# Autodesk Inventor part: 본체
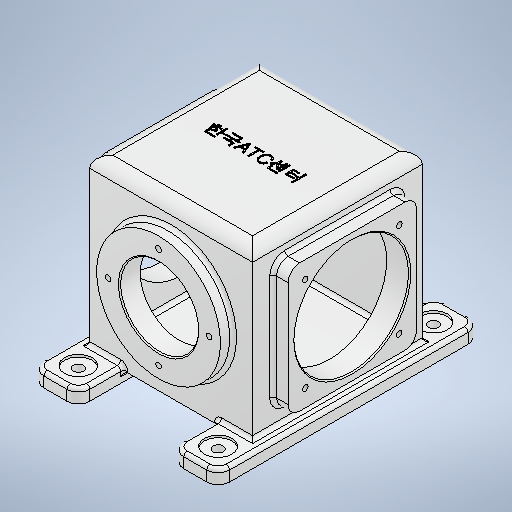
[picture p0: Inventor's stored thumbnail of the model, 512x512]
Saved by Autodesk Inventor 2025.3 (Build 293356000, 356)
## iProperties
Created: 2026-01
Part Number: 본체
Material: 알루미늄 6061
Document SubType Name: Modeling
Designer: PC01-12
Density: 2.7 g/cm^3
Appearance: 알루미늄 - 평지
Mass: 2756.19 g
Surface Area: 2492.21 cm^2
Volume: 1020.81 cm^3
Author: PC01-12
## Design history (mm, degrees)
sketch "스케치1"
  geometry: L1 (-71, -74)-(71, -74); L2 (71, -74)-(71, 74); L3 (71, 74)-(-71, 74); L4 (-71, 74)-(-71, -74); L5 (-71, -74)-(71, 74); L6 (71, -74)-(-71, 74); 1 further point
  constraints: 12 end point, 2 midpoint, 2 parallel, 1 horizontal, 1 perpendicular
  dimensions: "d0" = 142 distance of L3.end L2.end; "d1" = 148 distance of L2.end L1.end
extrude "돌출1" new body sketch "스케치1" stored distance "d2" = 148; taper "d3" = 0 deg
sketch "스케치2"
  geometry: C1 r 54 at (0, 0); 1 further point
  constraints: 1 centre point, 1 coincident
  dimensions: "d4" = 108 diameter of C1
extrude "돌출2" join sketch "스케치2" distance "d5" = 11; taper "d6" = 0 deg
sketch "스케치3"
  geometry: C1 r 34 at (0, 0); 1 further point
  constraints: 1 centre point, 1 coincident
  dimensions: "d7" = 68 diameter of C1
extrude "돌출3" cut sketch "스케치3" distance "d8" = 50; taper "d9" = 0 deg
sketch "스케치4" dims "d10" = 88
  geometry: 3 further points
  constraints: 2 vertical alignment, 1 coincident, 2 other
hole "구멍1" sketch "스케치4" at (0, 44) diameter "d11" = 4.917; stored, may be unused: countersink angle "d15" = 90 deg, drill point angle "d17" = 118 deg; dims "d12" = 12, "d13" = 4, "d14" = 2, "d16" = 14
sketch "스케치5"
  geometry: L1 (148, 148)-(0, 148) reference; L2 (0, 0)-(0, 148) reference; L3 (0, 0)-(148, 0) reference; L4 (148, 148)-(148, 0) reference; L5 (18, 130)-(130, 130); L6 (130, 130)-(130, 18); L7 (130, 18)-(18, 18); L8 (18, 18)-(18, 130); 1 further point
  constraints: 8 end point, 3 other
  dimensions: "d43" = 112 distance of L5.start L5.end
extrude "돌출4" join sketch "스케치5" distance "d22" = 13; taper "d23" = 0 deg
sketch "스케치6"
  geometry: C1 r 50 at (74, 74); 1 further point
  constraints: 1 centre point, 1 coincident
  dimensions: "d24" = 100 diameter of C1
extrude "돌출5" cut sketch "스케치6" stored distance "d25" = 148; taper "d26" = 0 deg
sketch "스케치7"
  geometry: L1 (18, 18)-(130, 18) reference; L2 (130, 18)-(130, 130) reference; L3 (130, 130)-(18, 130) reference; L4 (18, 130)-(18, 18) reference; L5 (33, 115)-(115, 115); L6 (115, 115)-(115, 33); L7 (115, 33)-(33, 33); L8 (33, 33)-(33, 115); C1 r 50 at (74, 74) reference; 5 further points
  constraints: 8 end point, 4 coincident, 3 other
  dimensions: "d44" = 82 distance of L5.start L5.end
hole "구멍2" sketch "스케치7" at (33, 115), (115, 115), (115, 33), (33, 33) diameter "d28" = 4.917; stored, may be unused: countersink angle "d32" = 90 deg, drill point angle "d34" = 118 deg; dims "d29" = 12, "d30" = 4, "d31" = 2, "d33" = 14
node "작업 평면1"
sketch "스케치8"
  geometry: L1 (-41, 114)-(-81, 114); L2 (-81, 114)-(-81, -114); L3 (-81, -114)-(-41, -114); L4 (-41, -114)-(-41, 114); L5 (81, 114)-(41, 114); L6 (41, 114)-(41, -114); L7 (41, -114)-(81, -114); L8 (81, -114)-(81, 114); L9 (0, -105.8)-(0, 116.8) reference; L10 (117.6, 0)-(-117.6, 0) reference; 1 further point
  constraints: 16 end point, 4 parallel, 2 horizontal, 2 perpendicular, 3 other
  dimensions: "d36" = 162 distance between parallel lines of L2 L8; "d37" = 40 distance between parallel lines of L6 L8; "d38" = 40 distance between parallel lines of L2 L4; "d39" = 228 distance between parallel lines of L1 L3; "d40" = 228 distance between parallel lines of L7 L5
extrude "돌출6" join sketch "스케치8" distance "d41" = 12; taper "d42" = 0 deg
sketch "스케치9"
  geometry: L1 (-61, -94)-(61, -94); L2 (61, -94)-(61, 94); L3 (61, 94)-(-61, 94); L4 (-61, 94)-(-61, -94); L5 (-61, -94)-(61, 94); L6 (61, -94)-(-61, 94); C1 r 12 at (-61, 94); C2 r 12 at (61, 94); C3 r 12 at (61, -94); C4 r 12 at (-61, -94); 1 further point
  constraints: 12 end point, 4 centre point, 4 coincident, 2 midpoint, 2 parallel, 1 horizontal, 1 perpendicular
  dimensions: "d46" = 122 distance of L3.end L2.end; "d47" = 188 distance of L2.end L1.end; "d48" = 24 diameter of C1; "d49" = 24 diameter of C2; "d50" = 24 diameter of C3; "d51" = 24 diameter of C4
extrude "돌출7" cut sketch "스케치9" distance "d52" = 2; taper "d53" = 0 deg
sketch "스케치10"
  geometry: L1 (0, -188)-(122, -188); L2 (122, -188)-(122, 0); L3 (122, 0)-(0, 0); L4 (0, 0)-(0, -188); L5 (0, -188)-(122, 0); L6 (122, -188)-(0, 0); C1 r 4.5 at (0, 0); C2 r 4.5 at (122, 0); C3 r 4.5 at (122, -188); C4 r 4.5 at (0, -188); 1 further point
  constraints: 12 end point, 4 centre point, 4 coincident, 2 midpoint, 2 parallel, 1 horizontal, 1 perpendicular
  dimensions: "d54" = 122 distance of L3.end L2.end; "d55" = 188 distance of L2.end L1.end; "d56" = 9 diameter of C1; "d57" = 9 diameter of C2; "d58" = 9 diameter of C3; "d59" = 9 diameter of C4
extrude "돌출8" cut sketch "스케치10" distance "d60" = 10; taper "d61" = 0 deg
fillet "모깎기2" dims "d62" = 3
fillet "모깎기3" dims "d63" = 10
chamfer "모따기1" distance "d65" = 1; stored, may be unused: second distance "d66" = 2, angle "d67" = 45 deg
fillet "모깎기5" dims "d68" = 10
fillet "모깎기6" dims "d69" = 3
fillet "모깎기7" dims "d70" = 3
fillet "모깎기8" dims "d71" = 10
sketch "스케치11"
  geometry: L1 (19.247, -58.543)-(102.205, -58.543); L2 (102.205, -58.543)-(102.205, -70.551); L3 (102.205, -70.551)-(19.247, -70.551); L4 (19.247, -70.551)-(19.247, -58.543); 1 further point
  constraints: 2 other
feature "엠보싱1" sketch "스케치11" dims "d0" = 142, "d1" = 148, "d12" = 12, "d72" = 0.5, "d73" = 0
sketch "스케치12"
  geometry: L1 (61, -67)-(-61, -67); L2 (-64, -64)-(-64, 64); L3 (-61, 67)-(61, 67); L4 (64, 64)-(64, -64); L5 (64, -67)-(-64, 67); L6 (-64, -67)-(64, 67); A1 r 3 centre (-61, -64) between (-64, -64) and (-61, -67); A2 r 3 centre (61, -64) between (61, -67) and (64, -64); A3 r 3 centre (61, 64) between (64, 64) and (61, 67); A4 r 3 centre (-61, 64) between (-61, 67) and (-64, 64); 1 further point
  constraints: 12 end point, 8 point on circle, 8 point on line, 8 tangent, 4 centre point, 2 midpoint, 2 parallel, 1 horizontal, 1 perpendicular
  dimensions: "d74" = 128 distance of L5.end L6.end; "d75" = 134 distance of L6.start L5.end; "d78" = 3 radius of A1; "d79" = 3 radius of A2; "d80" = 3 radius of A3 (derived); "d81" = 3 radius of A4 (derived)
extrude "돌출9" cut sketch "스케치12" stored distance "d76" = 134; taper "d77" = 0 deg
fillet "모깎기9" dims "d82" = 3
node "솔리드1"
pattern_circular "원형 패턴1" dims angle "d19" = 360 deg
mirror "미러1"
mirror "미러2"
node "투영된 루프1"
node "투영된 루프2"
feature "A9D066F2-1C7D-4E18-AEED-F7BC21143FA4" dims "d11" = 4.917, "d12" = 12, "d13" = 4, "d14" = 2, "d15" = 90 deg, "d16" = 14, "d17" = 118 deg
other parameters: "d35" = -82
